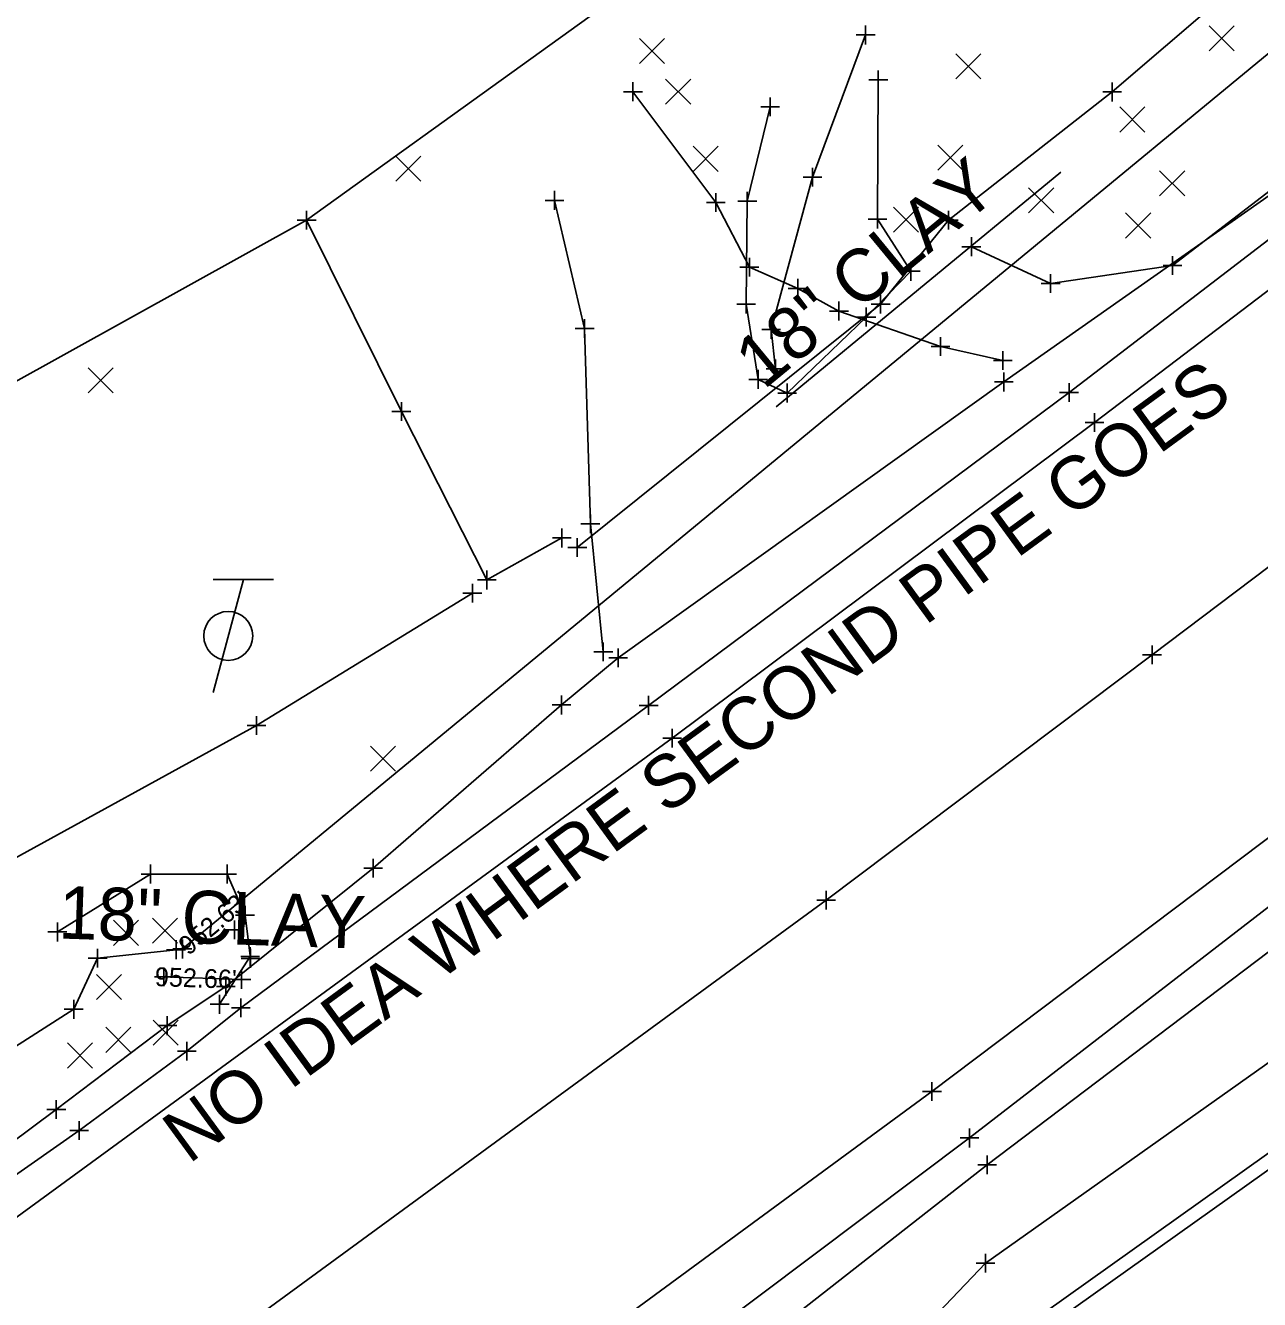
# Model space of a CAD drawing. Extents: x -4 to 139204, y -4 to 477121.
# Drawn here: x 138969.9 to 139035.5, y 476927 to 476994.7 of the extents above; entities that cross this region are included whole.
import ezdxf

# ---------------------------------------------------------------- set-up
doc = ezdxf.new("R2010")
doc.units = 0
for name, color, linetype in [('DR_X_Ditch', 7, 'Continuous'), ('DR_X_Storm_Sewer', 7, 'Continuous'), ('DR_X_Text', 7, 'Continuous'), ('GE_X_Alignment', 7, 'Continuous'), ('GE_X_Alignment_100_Bearings', 7, 'Continuous'), ('GE_X_Alignment_100_Distances', 7, 'Continuous'), ('GE_X_Alignment_100_Stations', 7, 'Continuous'), ('PM_X_Edge_Line', 7, 'Continuous'), ('PM_X_Surveyed_Line', 7, 'Continuous'), ('PV_X_COP', 7, 'Continuous'), ('PV_X_Driveway', 7, 'Continuous'), ('PV_X_EOP', 7, 'Continuous'), ('PV_X_Shoulder', 7, 'Continuous'), ('PV_X_Shoulder_Aggregate', 7, 'Continuous'), ('RD_X_Fence', 7, 'Continuous'), ('RD_X_Gate', 7, 'Continuous'), ('RD_X_GR_Lt', 7, 'Continuous'), ('SC_Scratch1', 7, 'Continuous'), ('SV_X_Terrain_Boundary', 7, 'Continuous'), ('SV_X_Text', 7, 'Continuous')]:
    doc.layers.add(name, color=color, linetype=linetype)

msp = doc.modelspace()

# ---------------------------------------------------------------- linework, layer by layer
at = {"layer": 'DR_X_Ditch'}
for points in [[(139084.31, 476969.071), (139079.627, 476963.915), (139073.397, 476959.844), (139063.705, 476954.01), (139045.774, 476940.83), (139023.925, 476925.276), (139007.837, 476912.933)], [(138977.947, 476945.562), (138973.78, 476945.109), (138972.508, 476942.396), (138962.393, 476935.946), (138947.336, 476924.656), (138919.117, 476904.767)]]:
    msp.add_lwpolyline(points, dxfattribs=at)
at = {"layer": 'DR_X_Storm_Sewer'}
for p, q in [((138978.284, 476945.603), (139056.168, 477009.808)), ((138907.351, 476843.166), (139091.624, 476974.362)), ((138907.351, 476843.166), (139091.624, 476974.362)), ((138977.296, 476944.116), (138981.42, 476943.976))]:
    msp.add_line(p, q, dxfattribs=at)
at = {"layer": 'DR_X_Text'}
msp.add_line((139024.966, 476986.872), (139009.837, 476974.401), dxfattribs=at)
at = {"layer": 'GE_X_Alignment'}
for p, q in [((139032.845, 476993.315), (139034.179, 476994.65)), ((139032.845, 476994.65), (139034.179, 476993.315)), ((139002.569, 476992.644), (139003.903, 476993.978)), ((139002.569, 476993.978), (139003.903, 476992.644)), ((139019.375, 476991.834), (139020.709, 476993.169)), ((139019.375, 476993.169), (139020.709, 476991.834)), ((139003.96, 476990.482), (139005.294, 476991.818)), ((139003.96, 476991.818), (139005.294, 476990.482)), ((139028.097, 476989.004), (139029.431, 476990.34)), ((139028.097, 476990.34), (139029.431, 476989.004)), ((139005.423, 476986.914), (139006.757, 476988.249)), ((139005.423, 476988.249), (139006.757, 476986.914)), ((139018.427, 476986.979), (139019.761, 476988.314)), ((139018.427, 476988.314), (139019.761, 476986.979)), ((138989.617, 476986.389), (138990.951, 476987.723)), ((138989.617, 476987.723), (138990.951, 476986.389)), ((139030.21, 476985.619), (139031.544, 476986.954)), ((139030.21, 476986.954), (139031.544, 476985.619)), ((139023.253, 476984.709), (139024.587, 476986.043)), ((139023.253, 476986.043), (139024.587, 476984.709)), ((139016.072, 476983.683), (139017.406, 476985.019)), ((139016.072, 476985.019), (139017.406, 476983.683)), ((139028.405, 476983.373), (139029.739, 476984.709)), ((139028.405, 476984.709), (139029.739, 476983.373)), ((138973.268, 476975.152), (138974.602, 476976.487)), ((138973.268, 476976.487), (138974.602, 476975.152)), ((138988.275, 476955.051), (138989.609, 476956.385)), ((138988.275, 476956.385), (138989.609, 476955.051)), ((138974.616, 476945.793), (138975.95, 476947.128)), ((138974.616, 476947.128), (138975.95, 476945.793)), ((138976.688, 476945.903), (138978.022, 476947.238)), ((138976.688, 476947.238), (138978.022, 476945.903)), ((138973.719, 476942.918), (138975.053, 476944.253)), ((138973.719, 476944.253), (138975.053, 476942.918)), ((138974.217, 476940.102), (138975.551, 476941.438)), ((138974.217, 476941.438), (138975.551, 476940.102)), ((138976.732, 476940.487), (138978.066, 476941.823)), ((138976.732, 476941.823), (138978.066, 476940.487)), ((138972.176, 476939.271), (138973.51, 476940.606)), ((138972.176, 476940.606), (138973.51, 476939.271))]:
    msp.add_line(p, q, dxfattribs=at)
at = {"layer": 'GE_X_Alignment_100_Bearings'}
for p, q in [((139014.091, 476994.165), (139015.091, 476994.165)), ((139014.591, 476994.665), (139014.591, 476993.665)), ((139014.591, 476994.165), (139014.591, 476994.165)), ((139015.263, 476992.276), (139015.263, 476991.276)), ((139002.228, 476991.649), (139002.228, 476990.649)), ((139014.763, 476991.776), (139015.763, 476991.776)), ((139015.263, 476991.776), (139015.263, 476991.776)), ((139027.688, 476991.635), (139027.688, 476990.635)), ((139001.728, 476991.149), (139002.728, 476991.149)), ((139002.228, 476991.149), (139002.228, 476991.149)), ((139009.518, 476990.842), (139009.518, 476989.842)), ((139027.188, 476991.135), (139028.188, 476991.135)), ((139027.688, 476991.135), (139027.688, 476991.135)), ((139009.018, 476990.342), (139010.018, 476990.342)), ((139009.518, 476990.342), (139009.518, 476990.342)), ((139011.266, 476986.609), (139012.266, 476986.609)), ((139011.766, 476987.109), (139011.766, 476986.109)), ((139011.766, 476986.609), (139011.766, 476986.609)), ((138997.558, 476985.377), (138998.558, 476985.377)), ((138998.058, 476985.877), (138998.058, 476984.877)), ((138998.058, 476985.377), (138998.058, 476985.377)), ((139006.129, 476985.266), (139007.129, 476985.266)), ((139006.629, 476985.766), (139006.629, 476984.766)), ((139006.629, 476985.266), (139006.629, 476985.266)), ((139007.8, 476985.331), (139008.8, 476985.331)), ((139008.3, 476985.831), (139008.3, 476984.831)), ((139008.3, 476985.331), (139008.3, 476985.331)), ((138984.887, 476984.824), (138984.887, 476983.824)), ((139015.223, 476984.883), (139015.223, 476983.883)), ((139019.001, 476984.821), (139019.001, 476983.821)), ((138984.387, 476984.324), (138985.387, 476984.324)), ((138984.887, 476984.324), (138984.887, 476984.324)), ((139014.723, 476984.383), (139015.723, 476984.383)), ((139015.223, 476984.383), (139015.223, 476984.383)), ((139018.501, 476984.321), (139019.501, 476984.321)), ((139019.001, 476984.321), (139019.001, 476984.321)), ((139020.21, 476983.413), (139020.21, 476982.413)), ((139019.71, 476982.913), (139020.71, 476982.913)), ((139020.21, 476982.913), (139020.21, 476982.913)), ((139007.913, 476981.824), (139008.913, 476981.824)), ((139008.413, 476982.324), (139008.413, 476981.324)), ((139008.413, 476981.824), (139008.413, 476981.824)), ((139016.99, 476982.109), (139016.99, 476981.109)), ((139030.398, 476981.914), (139031.398, 476981.914)), ((139030.898, 476982.414), (139030.898, 476981.414)), ((139030.898, 476981.914), (139030.898, 476981.914)), ((139010.981, 476981.2), (139010.981, 476980.2)), ((139016.49, 476981.609), (139017.49, 476981.609)), ((139016.99, 476981.609), (139016.99, 476981.609)), ((139024.42, 476981.458), (139024.42, 476980.458)), ((139010.481, 476980.7), (139011.481, 476980.7)), ((139010.981, 476980.7), (139010.981, 476980.7)), ((139023.92, 476980.958), (139024.92, 476980.958)), ((139024.42, 476980.958), (139024.42, 476980.958)), ((139007.738, 476979.865), (139008.738, 476979.865)), ((139008.238, 476980.365), (139008.238, 476979.365)), ((139008.238, 476979.865), (139008.238, 476979.865)), ((139013.172, 476979.996), (139013.172, 476978.996)), ((139014.888, 476979.86), (139015.888, 476979.86)), ((139015.388, 476980.36), (139015.388, 476979.36)), ((139015.388, 476979.86), (139015.388, 476979.86)), ((139012.672, 476979.496), (139013.672, 476979.496)), ((139013.172, 476979.496), (139013.172, 476979.496)), ((139014.124, 476979.177), (139015.124, 476979.177)), ((139014.624, 476979.677), (139014.624, 476978.677)), ((139014.624, 476979.177), (139014.624, 476979.177)), ((138999.158, 476978.569), (139000.158, 476978.569)), ((138999.658, 476979.069), (138999.658, 476978.069)), ((138999.658, 476978.569), (138999.658, 476978.569)), ((139009.074, 476978.519), (139010.074, 476978.519)), ((139009.574, 476979.019), (139009.574, 476978.019)), ((139009.574, 476978.519), (139009.574, 476978.519)), ((139018.573, 476978.115), (139018.573, 476977.115)), ((139018.073, 476977.615), (139019.073, 476977.615)), ((139018.573, 476977.615), (139018.573, 476977.615)), ((139021.884, 476977.364), (139021.884, 476976.364)), ((139009.302, 476976.424), (139010.302, 476976.424)), ((139009.802, 476976.924), (139009.802, 476975.924)), ((139009.802, 476976.424), (139009.802, 476976.424)), ((139021.384, 476976.864), (139022.384, 476976.864)), ((139021.884, 476976.864), (139021.884, 476976.864)), ((139008.376, 476975.864), (139009.376, 476975.864)), ((139008.876, 476976.364), (139008.876, 476975.364)), ((139008.876, 476975.864), (139008.876, 476975.864)), ((139021.43, 476975.729), (139022.43, 476975.729)), ((139021.93, 476976.229), (139021.93, 476975.229)), ((139021.93, 476975.729), (139021.93, 476975.729)), ((139009.924, 476975.138), (139010.924, 476975.138)), ((139010.424, 476975.638), (139010.424, 476974.638)), ((139010.424, 476975.138), (139010.424, 476975.138)), ((139024.901, 476975.169), (139025.901, 476975.169)), ((139025.401, 476975.669), (139025.401, 476974.669)), ((139025.401, 476975.169), (139025.401, 476975.169)), ((138989.921, 476974.661), (138989.921, 476973.661)), ((138989.421, 476974.161), (138990.421, 476974.161)), ((138989.921, 476974.161), (138989.921, 476974.161)), ((139026.754, 476974.072), (139026.754, 476973.072)), ((139026.754, 476974.072), (139026.754, 476973.072)), ((139026.254, 476973.572), (139027.254, 476973.572)), ((139026.254, 476973.572), (139027.254, 476973.572)), ((139026.754, 476973.572), (139026.754, 476973.572)), ((139026.754, 476973.572), (139026.754, 476973.572)), ((138999.963, 476968.689), (138999.963, 476967.689)), ((138998.448, 476967.94), (138998.448, 476966.94)), ((138999.463, 476968.189), (139000.463, 476968.189)), ((138999.963, 476968.189), (138999.963, 476968.189)), ((138997.948, 476967.44), (138998.948, 476967.44)), ((138998.448, 476967.44), (138998.448, 476967.44)), ((138998.768, 476966.93), (138999.768, 476966.93)), ((138999.268, 476967.43), (138999.268, 476966.43)), ((138999.268, 476966.93), (138999.268, 476966.93)), ((138994.464, 476965.707), (138994.464, 476964.707)), ((138993.691, 476965.008), (138993.691, 476964.008)), ((138993.964, 476965.207), (138994.964, 476965.207)), ((138994.464, 476965.207), (138994.464, 476965.207)), ((138993.191, 476964.508), (138994.191, 476964.508)), ((138993.691, 476964.508), (138993.691, 476964.508)), ((139000.649, 476961.89), (139000.649, 476960.89)), ((139001.441, 476961.57), (139001.441, 476960.57)), ((139029.811, 476961.733), (139029.811, 476960.733)), ((139029.811, 476961.733), (139029.811, 476960.733)), ((139000.149, 476961.39), (139001.149, 476961.39)), ((139000.649, 476961.39), (139000.649, 476961.39)), ((139000.941, 476961.07), (139001.941, 476961.07)), ((139001.441, 476961.07), (139001.441, 476961.07)), ((139029.311, 476961.233), (139030.311, 476961.233)), ((139029.311, 476961.233), (139030.311, 476961.233)), ((139029.811, 476961.233), (139029.811, 476961.233)), ((139029.811, 476961.233), (139029.811, 476961.233)), ((138998.433, 476959.067), (138998.433, 476958.067)), ((139003.06, 476959.042), (139003.06, 476958.042)), ((138997.933, 476958.567), (138998.933, 476958.567)), ((138998.433, 476958.567), (138998.433, 476958.567)), ((139002.56, 476958.542), (139003.56, 476958.542)), ((139003.06, 476958.542), (139003.06, 476958.542)), ((138981.718, 476957.473), (138982.718, 476957.473)), ((138982.218, 476957.973), (138982.218, 476956.973)), ((138982.218, 476957.473), (138982.218, 476957.473)), ((139003.814, 476956.805), (139004.814, 476956.805)), ((139003.814, 476956.805), (139004.814, 476956.805)), ((139004.314, 476957.305), (139004.314, 476956.305)), ((139004.314, 476957.305), (139004.314, 476956.305)), ((139004.314, 476956.805), (139004.314, 476956.805)), ((139004.314, 476956.805), (139004.314, 476956.805)), ((138976.596, 476950.083), (138976.596, 476949.083)), ((138980.658, 476950.081), (138980.658, 476949.081)), ((138988.422, 476950.397), (138988.422, 476949.397)), ((138976.096, 476949.583), (138977.096, 476949.583)), ((138976.596, 476949.583), (138976.596, 476949.583)), ((138980.158, 476949.581), (138981.158, 476949.581)), ((138980.658, 476949.581), (138980.658, 476949.581)), ((138987.922, 476949.897), (138988.922, 476949.897)), ((138988.422, 476949.897), (138988.422, 476949.897)), ((139012.493, 476948.698), (139012.493, 476947.698)), ((139012.493, 476948.698), (139012.493, 476947.698)), ((139011.993, 476948.198), (139012.993, 476948.198)), ((139011.993, 476948.198), (139012.993, 476948.198)), ((139012.493, 476948.198), (139012.493, 476948.198)), ((139012.493, 476948.198), (139012.493, 476948.198)), ((138981.114, 476947.394), (138982.114, 476947.394)), ((138981.614, 476947.894), (138981.614, 476946.894)), ((138981.614, 476947.394), (138981.614, 476947.394)), ((138971.64, 476947.004), (138971.64, 476946.004)), ((138971.14, 476946.504), (138972.14, 476946.504)), ((138971.64, 476946.504), (138971.64, 476946.504)), ((138977.947, 476946.062), (138977.947, 476945.062)), ((138973.78, 476945.609), (138973.78, 476944.609)), ((138977.447, 476945.562), (138978.447, 476945.562)), ((138977.947, 476945.562), (138977.947, 476945.562)), ((138981.888, 476945.704), (138981.888, 476944.704)), ((138981.899, 476945.601), (138981.899, 476944.601)), ((138973.28, 476945.109), (138974.28, 476945.109)), ((138973.78, 476945.109), (138973.78, 476945.109)), ((138981.388, 476945.204), (138982.388, 476945.204)), ((138981.399, 476945.101), (138982.399, 476945.101)), ((138981.888, 476945.204), (138981.888, 476945.204)), ((138981.899, 476945.101), (138981.899, 476945.101)), ((138980.594, 476944.11), (138980.594, 476943.11)), ((138980.094, 476943.61), (138981.094, 476943.61)), ((138980.594, 476943.61), (138980.594, 476943.61)), ((138972.508, 476942.896), (138972.508, 476941.896)), ((138979.764, 476942.661), (138980.764, 476942.661)), ((138980.264, 476943.161), (138980.264, 476942.161)), ((138980.264, 476942.661), (138980.264, 476942.661)), ((138981.386, 476942.976), (138981.386, 476941.976)), ((138972.008, 476942.396), (138973.008, 476942.396)), ((138972.508, 476942.396), (138972.508, 476942.396)), ((138977.481, 476942.026), (138977.481, 476941.026)), ((138980.886, 476942.476), (138981.886, 476942.476)), ((138981.386, 476942.476), (138981.386, 476942.476)), ((138976.981, 476941.526), (138977.981, 476941.526)), ((138977.481, 476941.526), (138977.481, 476941.526)), ((138978.522, 476940.669), (138978.522, 476939.669)), ((138978.022, 476940.169), (138979.022, 476940.169)), ((138978.522, 476940.169), (138978.522, 476940.169)), ((139018.116, 476938.523), (139018.116, 476937.523)), ((139018.116, 476938.523), (139018.116, 476937.523)), ((139017.616, 476938.023), (139018.616, 476938.023)), ((139017.616, 476938.023), (139018.616, 476938.023)), ((139018.116, 476938.023), (139018.116, 476938.023)), ((139018.116, 476938.023), (139018.116, 476938.023)), ((138971.584, 476937.569), (138971.584, 476936.569)), ((138971.084, 476937.069), (138972.084, 476937.069)), ((138971.584, 476937.069), (138971.584, 476937.069)), ((138972.298, 476935.952), (138973.298, 476935.952)), ((138972.798, 476936.452), (138972.798, 476935.452)), ((138972.798, 476935.952), (138972.798, 476935.952)), ((139020.106, 476936.061), (139020.106, 476935.061)), ((139019.606, 476935.561), (139020.606, 476935.561)), ((139020.106, 476935.561), (139020.106, 476935.561)), ((139021.044, 476934.627), (139021.044, 476933.627)), ((139020.544, 476934.127), (139021.544, 476934.127)), ((139021.044, 476934.127), (139021.044, 476934.127)), ((139020.962, 476929.405), (139020.962, 476928.405)), ((139020.462, 476928.905), (139021.462, 476928.905)), ((139020.962, 476928.905), (139020.962, 476928.905))]:
    msp.add_line(p, q, dxfattribs=at)
at = {"layer": 'GE_X_Alignment_100_Distances'}
for p, q in [((138981.048, 476947.114), (138981.048, 476946.114)), ((138978.284, 476946.103), (138978.284, 476945.103)), ((138980.548, 476946.614), (138981.548, 476946.614)), ((138981.048, 476946.614), (138981.048, 476946.614)), ((138977.784, 476945.603), (138978.784, 476945.603)), ((138978.284, 476945.603), (138978.284, 476945.603)), ((138977.296, 476944.616), (138977.296, 476943.616)), ((138976.796, 476944.116), (138977.796, 476944.116)), ((138977.296, 476944.116), (138977.296, 476944.116)), ((138980.92, 476943.976), (138981.92, 476943.976)), ((138981.42, 476944.476), (138981.42, 476943.476)), ((138981.42, 476943.976), (138981.42, 476943.976))]:
    msp.add_line(p, q, dxfattribs=at)
at = {"layer": 'GE_X_Alignment_100_Stations'}
for p, q in [((138981.523, 476965.235), (138979.917, 476959.235)), ((138983.123, 476965.235), (138979.923, 476965.235))]:
    msp.add_line(p, q, dxfattribs=at)
msp.add_circle((138980.72, 476962.235), 1.3, dxfattribs=at)
at = {"layer": 'PM_X_Edge_Line'}
for points in [[(138923.242, 476898.186), (138964.692, 476927.855), (139004.314, 476956.805), (139026.754, 476973.572), (139043.226, 476986.096), (139066.294, 477004.413), (139084.97, 477019.976), (139103.96, 477036.155), (139120.378, 477050.406), (139142.062, 477069.904), (139165.575, 477091.057)], [(139119.978, 477018.535), (139108.07, 477008.289), (139096.43, 476998.562), (139075.62, 476981.789), (139057.894, 476968.012), (139018.116, 476938.023), (138977.717, 476908.355), (138952.937, 476890.592), (138936.689, 476878.892)]]:
    msp.add_lwpolyline(points, dxfattribs=at)
at = {"layer": 'PM_X_Surveyed_Line'}
msp.add_lwpolyline([(138930.184, 476888.564), (138972.007, 476918.562), (139012.493, 476948.198), (139029.811, 476961.233), (139052.078, 476978.039), (139073.558, 476995.35), (139089.175, 477007.916), (139110.846, 477026.03), (139111.346, 477026.745)], dxfattribs=at)
at = {"layer": 'PV_X_COP'}
msp.add_lwpolyline([(138930.195, 476888.554), (138972.007, 476918.562), (139012.493, 476948.198), (139029.811, 476961.233), (139052.078, 476978.039), (139073.558, 476995.35), (139089.175, 477007.916), (139110.846, 477026.03), (139129.377, 477042.526), (139155.719, 477066.268), (139171.584, 477080.905)], dxfattribs=at)
at = {"layer": 'PV_X_Driveway'}
for points in [[(139002.228, 476991.149), (139006.629, 476985.266), (139008.413, 476981.824), (139010.981, 476980.7), (139013.172, 476979.496), (139018.573, 476977.615), (139021.884, 476976.864)], [(139000.649, 476961.39), (138999.963, 476968.189), (138999.658, 476978.569), (138998.058, 476985.377)]]:
    msp.add_lwpolyline(points, dxfattribs=at)
at = {"layer": 'PV_X_EOP'}
for points in [[(138923.266, 476898.028), (138964.692, 476927.855), (139004.314, 476956.805), (139026.754, 476973.572), (139043.226, 476986.096), (139066.294, 477004.413), (139084.97, 477019.976), (139103.96, 477036.155), (139120.378, 477050.406), (139142.062, 477069.904), (139165.559, 477091.096)], [(139119.987, 477018.511), (139108.07, 477008.289), (139096.43, 476998.562), (139075.62, 476981.789), (139057.894, 476968.012), (139018.116, 476938.023), (138977.717, 476908.355), (138952.937, 476890.592), (138936.542, 476879.008)]]:
    msp.add_lwpolyline(points, dxfattribs=at)
at = {"layer": 'PV_X_Shoulder'}
for points in [[(138921.874, 476900.032), (138963.408, 476929.378), (138972.798, 476935.952), (138978.522, 476940.169), (138981.386, 476942.476), (139003.06, 476958.542), (139025.401, 476975.169), (139041.935, 476987.828), (139065.015, 477005.945), (139083.976, 477021.177), (139103.138, 477037.313), (139119.211, 477051.78), (139140.599, 477071.456), (139163.948, 477092.808)], [(139183.638, 477072.424), (139153.919, 477045.299), (139136.787, 477030.023), (139126.343, 477020.832), (139109.649, 477006.831), (139097.905, 476996.885), (139077.102, 476979.89), (139059.387, 476965.891), (139020.106, 476935.561), (139003.351, 476922.965), (138997.924, 476918.666), (138993.965, 476914.098), (138990.512, 476910.309), (138981.306, 476903.856), (138956.564, 476885.614), (138940.343, 476873.773)]]:
    msp.add_lwpolyline(points, dxfattribs=at)
at = {"layer": 'PV_X_Shoulder_Aggregate'}
for points in [[(138921.157, 476900.979), (138962.753, 476930.499), (138971.584, 476937.069), (138977.481, 476941.526), (138980.594, 476943.61), (138988.422, 476949.897), (138998.433, 476958.567), (139001.441, 476961.07), (139021.93, 476975.729), (139041.029, 476989.148), (139064.316, 477006.715), (139083.388, 477021.859), (139091.2, 477028.559), (139091.618, 477030.237), (139093.456, 477032.075), (139094.302, 477031.202), (139095.586, 477032.478), (139102.652, 477038.046), (139118.491, 477052.663), (139139.94, 477072.231), (139163.129, 477093.583)], [(139124.206, 477016.86), (139110.781, 477005.495), (139098.924, 476995.454), (139078.061, 476978.654), (139060.667, 476964.123), (139021.044, 476934.127), (139004.817, 476921.429), (138999.267, 476916.949), (138995.343, 476912.815), (138991.494, 476909.144)]]:
    msp.add_lwpolyline(points, dxfattribs=at)
at = {"layer": 'RD_X_Fence'}
for p, q in [((138993.691, 476964.508), (138982.218, 476957.473)), ((138993.691, 476964.508), (138993.691, 476964.508)), ((138982.218, 476957.473), (138954.197, 476942.079))]:
    msp.add_line(p, q, dxfattribs=at)
for points in [[(139114.124, 477069.425), (139097.626, 477050.067), (139068.264, 477026.835), (139055.528, 477014.997), (139027.688, 476991.135), (139019.001, 476984.321), (139015.388, 476979.86)], [(138984.887, 476984.324), (138989.921, 476974.161), (138994.464, 476965.207), (138998.448, 476967.44)]]:
    msp.add_lwpolyline(points, dxfattribs=at)
at = {"layer": 'RD_X_Gate'}
msp.add_line((138999.268, 476966.93), (139015.388, 476979.86), dxfattribs=at)
at = {"layer": 'RD_X_GR_Lt'}
msp.add_lwpolyline([(139020.21, 476982.913), (139024.42, 476980.958), (139030.898, 476981.914), (139041.279, 476989.89), (139065.043, 477007.777), (139083.881, 477022.893), (139095.593, 477032.486), (139103.613, 477039.235), (139110.37, 477044.947), (139114.423, 477051.669), (139114.509, 477056.44)], dxfattribs=at)
at = {"layer": 'SC_Scratch1'}
for points in [[(139009.802, 476976.424), (139009.574, 476978.519), (139011.766, 476986.609), (139014.591, 476994.165)], [(139009.518, 476990.342), (139008.3, 476985.331), (139008.238, 476979.865), (139008.876, 476975.864), (139010.424, 476975.138), (139014.624, 476979.177), (139016.99, 476981.609), (139015.223, 476984.383), (139015.263, 476991.776)], [(139071.871, 476964.685), (139042.717, 476944.31), (139020.962, 476928.905), (139008.806, 476916.158), (139005.384, 476912.978), (138998.45, 476910.112), (138989.767, 476898.219), (138984.604, 476875.789)], [(138980.264, 476942.661), (138981.888, 476945.204), (138981.899, 476945.101), (138981.614, 476947.394), (138980.658, 476949.581), (138976.596, 476949.583), (138971.64, 476946.504)]]:
    msp.add_lwpolyline(points, dxfattribs=at)
at = {"layer": 'SV_X_Terrain_Boundary'}
msp.add_lwpolyline([(139046.155, 477077.639), (139022.377, 477019.422), (139008.72, 477001.491), (138984.887, 476984.324), (138943.596, 476961.432), (138909.516, 476935.685), (138901, 476928.007)], dxfattribs=at)

# ---------------------------------------------------------------- texts
at = {"layer": 'DR_X_Text'}
for rotation, p in [(39.50104, (139009.168, 476975.277)), (358.05569, (138971.663, 476946.16))]:
    msp.add_text('18" CLAY', height=2.8, rotation=rotation, dxfattribs=at).set_placement(p)
at = {"layer": 'SC_Scratch1'}
for s, rotation, p in [("952.63'", 39.50104, (138978.602, 476945.217)), ("952.66'", 358.05569, (138976.808, 476943.632))]:
    msp.add_text(s, height=1, rotation=rotation, dxfattribs=at).set_placement(p)
at = {"layer": 'SV_X_Text'}
msp.add_text('NO IDEA WHERE SECOND PIPE GOES', height=2.8, rotation=36.17931, dxfattribs=at).set_placement((138978.624, 476934.143))

doc.saveas('drawing.dxf')
